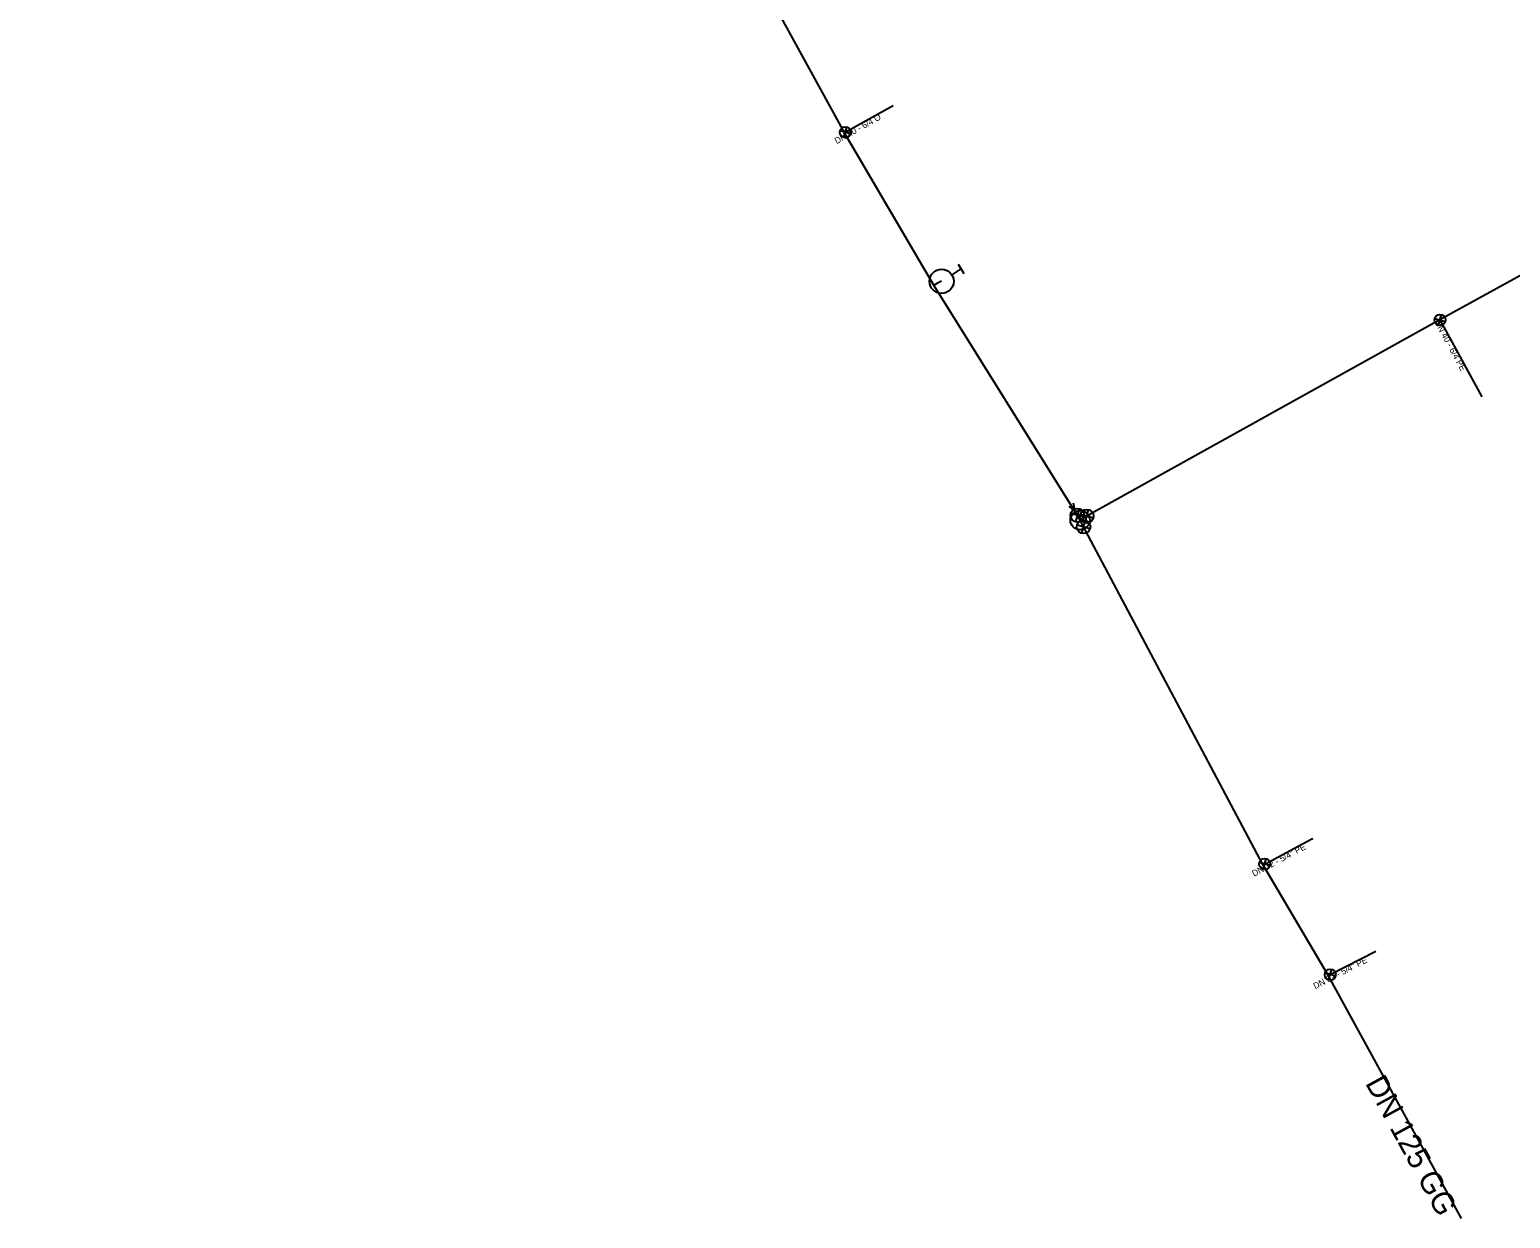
# Model space of a CAD drawing. Extents: x -443562 to -443270, y -1122830 to -1122511.
# Drawn here: x -443508.6 to -443400.8, y -1122829.6 to -1122743.1 of the extents above; entities that cross this region are included whole.
import ezdxf

# ---------------------------------------------------------------- set-up
doc = ezdxf.new("R2010")
doc.units = 0
for name, color, linetype in [('_hydrantova_odbocka_', 7, 'Continuous'), ('_pripojka_priblizne_', 7, 'Continuous'), ('_voda_smvak_prevzato_z_dokumentace_', 7, 'Continuous'), ('Default', 7, 'Continuous'), ('MoLevel 27', 7, 'Continuous'), ('MoLevel 28', 7, 'Continuous'), ('MoLevel 30', 7, 'Continuous'), ('MoLevel 32', 7, 'Continuous'), ('MoLevel 46', 7, 'Continuous'), ('MoLevel 53', 7, 'Continuous')]:
    doc.layers.add(name, color=color, linetype=linetype)

# ---------------------------------------------------------------- blocks, each defined once
blk = doc.blocks.new('_uzaver_')
at = {"layer": 'Default'}
for p, q in [((-0.000035, -0.000035), (0.000035, 0.000035)), ((0.000035, -0.000035), (-0.000035, 0.000035))]:
    blk.add_line(p, q, dxfattribs=at)
for radius in [0.00005, 0.0000025]:
    blk.add_circle((0, 0), radius, dxfattribs=at)
blk = doc.blocks.new('_uzaver_pripojka_')
at = {"layer": 'Default'}
for p, q in [((-0.000035, -0.000035), (0.000035, 0.000035)), ((0.000035, -0.000035), (-0.000035, 0.000035))]:
    blk.add_line(p, q, dxfattribs=at)
for radius in [0.00005, 0.0000025]:
    blk.add_circle((0, 0), radius, dxfattribs=at)
blk = doc.blocks.new('_hydrant_voda_')
at = {"layer": 'Default'}
for p, q in [((-0.0000225, 0.000095), (0.0000225, 0.000095)), ((0, 0.000095), (0, 0.00005))]:
    blk.add_line(p, q, dxfattribs=at)
blk.add_circle((0, 0), 0.00005, dxfattribs=at)
blk = doc.blocks.new('_sachta_voda_')
at = {"layer": 'Default'}
blk.add_lwpolyline([(-0.00001, 0.000065), (0, 0.000035), (0.00001, 0.000065)], dxfattribs=at)
blk.add_circle((0, 0), 0.000035, dxfattribs=at)

msp = doc.modelspace()

# ---------------------------------------------------------------- linework, layer by layer
at = {"layer": '_hydrantova_odbocka_'}
msp.add_lwpolyline([(-443442.24, -1122761.39), (-443442.53, -1122761.53), (-443442.81, -1122761.69)], dxfattribs=at)
at = {"layer": '_pripojka_priblizne_'}
msp.add_line((-443405.96, -1122764.2), (-443402.91, -1122769.8), dxfattribs=at)
for points in [[(-443449.31, -1122750.61), (-443449.25, -1122750.54), (-443445.77, -1122748.58)], [(-443418.85, -1122803.86), (-443418.72, -1122803.82), (-443415.29, -1122801.99), (-443415.18, -1122801.96)], [(-443414.07, -1122811.95), (-443413.95, -1122811.87), (-443410.64, -1122810.16)]]:
    msp.add_lwpolyline(points, dxfattribs=at)
at = {"layer": '_voda_smvak_prevzato_z_dokumentace_'}
for p, q in [((-443442.81, -1122761.69), (-443432.54, -1122778.15)), ((-443432.54, -1122778.15), (-443432.37, -1122778.43)), ((-443431.37, -1122778.33), (-443431.67, -1122778.5)), ((-443432.37, -1122778.43), (-443432.16, -1122778.78)), ((-443431.67, -1122778.5), (-443432.16, -1122778.78)), ((-443431.9, -1122779.26), (-443432.16, -1122778.78)), ((-443431.78, -1122779.48), (-443431.9, -1122779.26))]:
    msp.add_line(p, q, dxfattribs=at)
for points in [[(-443508.63, -1122645.88), (-443495.13, -1122671.4), (-443484.93, -1122687.61), (-443476.13, -1122703.74), (-443467.08, -1122719.85), (-443457.46, -1122735.74), (-443449.31, -1122750.61), (-443442.81, -1122761.69)], [(-443372, -1122744.61), (-443391.52, -1122756.26), (-443405.96, -1122764.2), (-443431.37, -1122778.33)], [(-443404.4, -1122829.62), (-443414.07, -1122811.95), (-443418.85, -1122803.86), (-443431.78, -1122779.48)]]:
    msp.add_lwpolyline(points, dxfattribs=at)

# ---------------------------------------------------------------- block references
at = {"layer": 'MoLevel 27'}
for p, xscale, yscale, rotation in [((-443432.36, -1122778.43), 9999.999999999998, 9999.999999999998, 120.027170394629), ((-443431.67, -1122778.5), 10000, 10000.000000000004, 29.806102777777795), ((-443431.9, -1122779.26), 10000, 9999.999999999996, -61.207295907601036)]:
    msp.add_blockref('_uzaver_', p, dxfattribs=dict(at, xscale=xscale, yscale=yscale, rotation=rotation))
at = {"layer": 'MoLevel 28', "xscale": 17636.68430335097, "yscale": 17636.684303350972, "rotation": -57.42594286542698}
msp.add_blockref('_hydrant_voda_', (-443442.24, -1122761.39), dxfattribs=at)
at = {"layer": 'MoLevel 30', "xscale": 20000, "yscale": 19999.999999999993, "rotation": 29.8107682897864}
msp.add_blockref('_sachta_voda_', (-443432.16, -1122778.78), dxfattribs=at)
at = {"layer": 'MoLevel 53'}
for p, xscale, yscale, rotation in [((-443449.25, -1122750.54), 7999.999999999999, 7999.999999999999, 29.47820952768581), ((-443405.96, -1122764.2), 8000, 8000, -61.39443239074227), ((-443418.72, -1122803.82), 8000, 7999.999999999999, 28.08115629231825), ((-443413.95, -1122811.87), 8000, 7999.999999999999, 27.321614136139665)]:
    msp.add_blockref('_uzaver_pripojka_', p, dxfattribs=dict(at, xscale=xscale, yscale=yscale, rotation=rotation))

# ---------------------------------------------------------------- texts
at = {"layer": 'MoLevel 32'}
for s, rotation, p in [('DN 40 - 6/4 O', 29.4782, (-443449.87, -1122751.41)), ('DN 40 - 6/4 PE', 298.6031, (-443406.38, -1122764.38)), ("DN 32 - 5/4'' PE", 28.0812, (-443419.49, -1122804.75)), ("DN 32 - 5/4'' PE", 27.3216, (-443415.04, -1122812.94))]:
    msp.add_text(s, height=0.455, rotation=rotation, dxfattribs=at).set_placement(p)
at = {"layer": 'MoLevel 46'}
msp.add_text('DN 125 GG', height=1.605, rotation=298.6999, dxfattribs=at).set_placement((-443411.43, -1122819.77))

doc.saveas('drawing.dxf')
